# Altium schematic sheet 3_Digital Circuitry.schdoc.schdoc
size 431 x 309 mm; Symbol: Sheet-Symbol-Custom; Device: Sheet-Symbol-Custom; @Page Count: 4; @Create Date: 2024-03-28; Drawn: Thomas Crisafulli; @Page No: 2; @Page Name: Digital Circuitry; @Project Name: OhmmeterV1.1_Release; @Schematic Name: Schematic 1; Page Size: A3; @Update Date: 2024-03-27
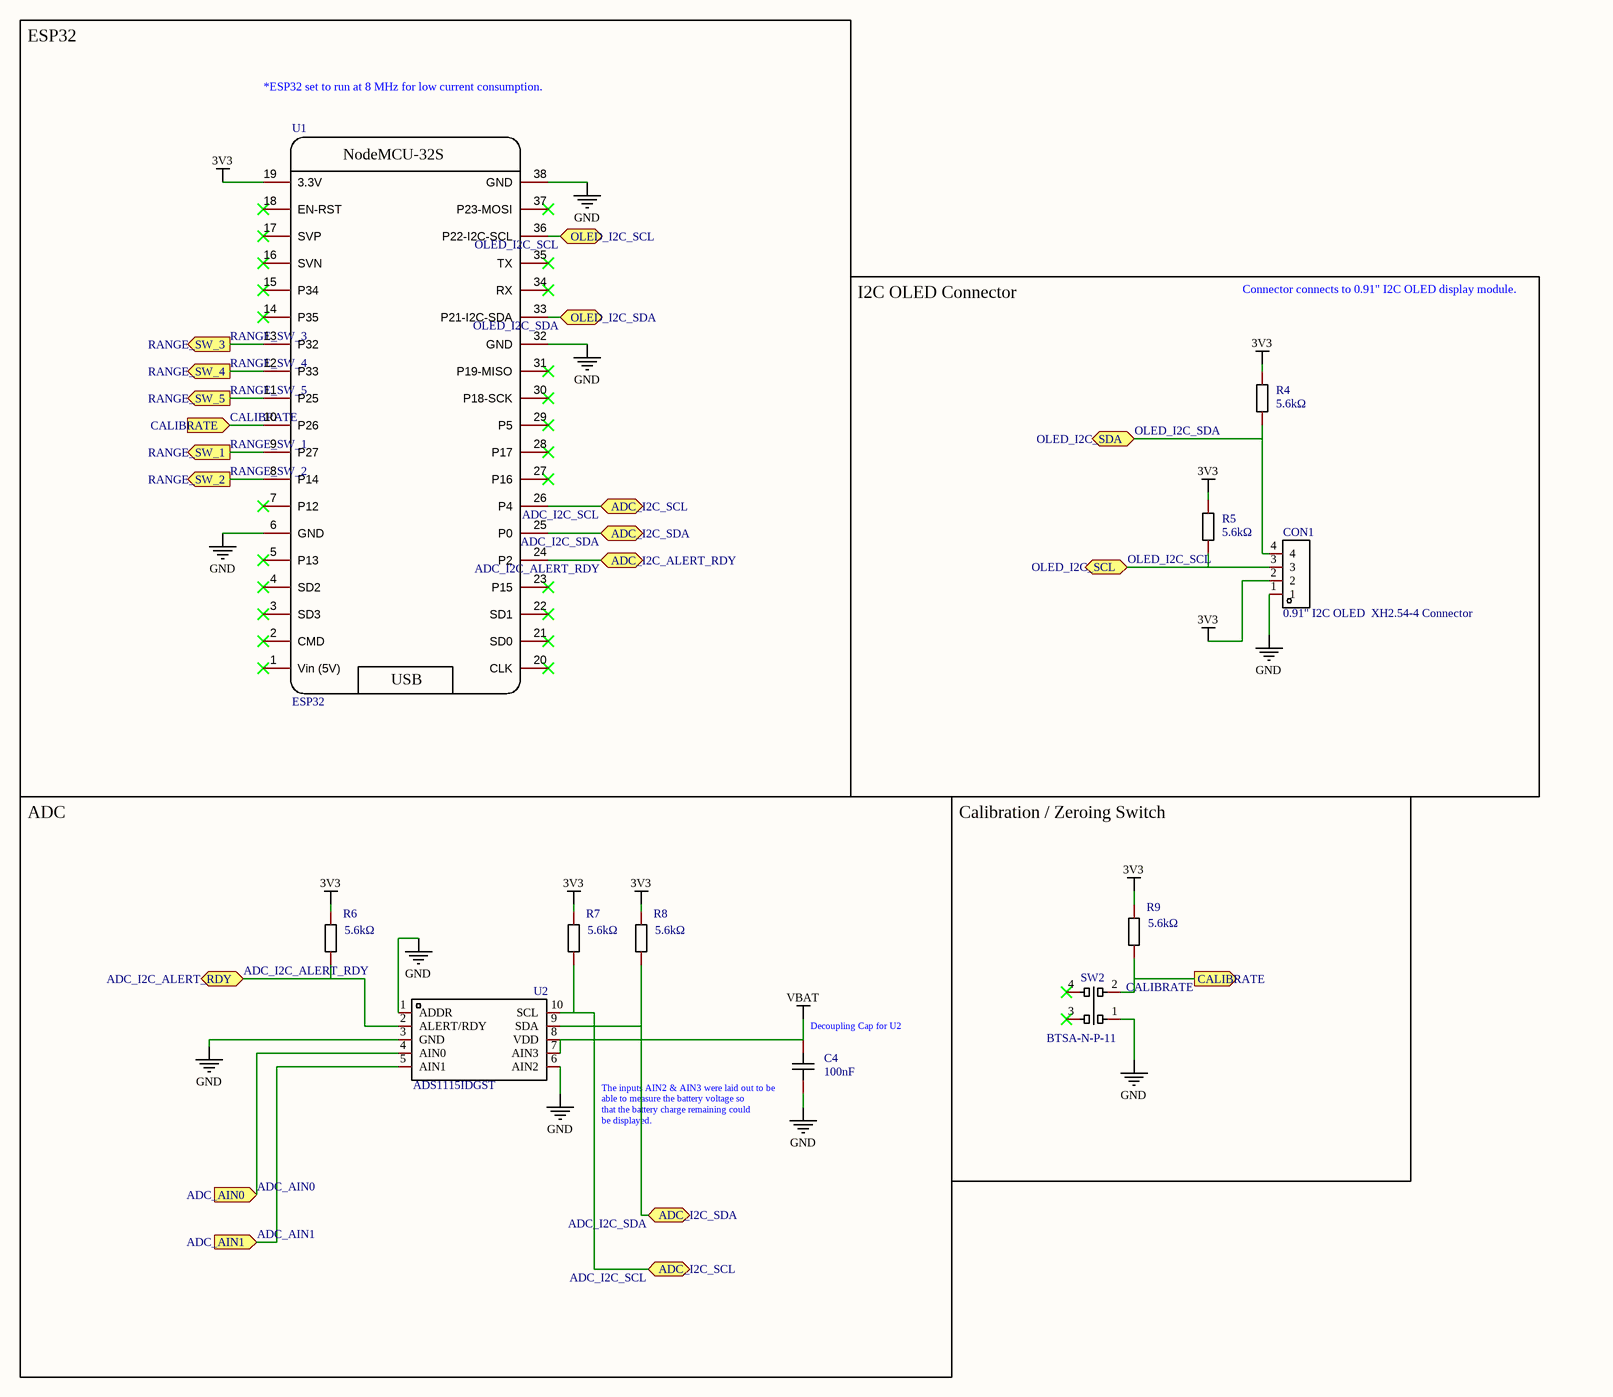
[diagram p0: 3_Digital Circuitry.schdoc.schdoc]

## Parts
C4  100nF  [C0603]
CON1  0.91" I2C OLED  XH2.54-4 Connector  [CONN-TH_XH2.54-4]
R4  5.6kΩ  [R0603]
R5  5.6kΩ  [R0603]
R6  5.6kΩ  [R0603]
R7  5.6kΩ  [R0603]
R8  5.6kΩ  [R0603]
R9  5.6kΩ  [R0603]
SW2  BTSA-N-P-11  [SW-TH_BTSA-X-P-11]
U1  ESP32  [NODEMCU-32SLUA]
U2  ADS1115IDGST  [VSSOP-10_L3.0-W3.0-P0.50-LS4.9-BL]

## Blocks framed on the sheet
ESP32: U1
I2C OLED Connector: CON1 R4 R5
ADC: C4 R6-R8 U2
Calibration / Zeroing Switch: R9 SW2

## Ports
ADC_AIN0 (in), ADC_AIN1 (in), ADC_I2C_ALERT_RDY (bidir), ADC_I2C_SCL (bidir), ADC_I2C_SDA (bidir), CALIBRATE (in), CALIBRATE (out), OLED_I2C_SCL (bidir), OLED_I2C_SDA (bidir), RANGE_SW_1 (out), RANGE_SW_2 (out), RANGE_SW_3 (out), RANGE_SW_4 (out), RANGE_SW_5 (out)

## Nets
3V3: CON1.2 R4.1 R5.2 R6.2 R7.2 R8.2 R9.2 U1.19(3.3V)
GND: C4.1 CON1.1 SW2.1 U1.6(GND) U1.32(GND) U1.38(GND) U2.1(ADDR) U2.3(GND) U2.6(AIN2)
VBAT: C4.2 U2.7(AIN3) U2.8(VDD)
ADC_AIN0: U2.4(AIN0) ; port ADC_AIN0
ADC_AIN1: U2.5(AIN1) ; port ADC_AIN1
ADC_I2C_ALERT_RDY: R6.1 U1.24(P2) U2.2(ALERT/RDY) ; port ADC_I2C_ALERT_RDY
ADC_I2C_SCL: R7.1 U1.26(P4) U2.10(SCL) ; port ADC_I2C_SCL
ADC_I2C_SDA: R8.1 U1.25(P0) U2.9(SDA) ; port ADC_I2C_SDA
CALIBRATE: R9.1 SW2.2 U1.10(P26) ; port CALIBRATE
OLED_I2C_SCL: CON1.3 R5.1 U1.36(P22-I2C-SCL) ; port OLED_I2C_SCL
OLED_I2C_SDA: CON1.4 R4.2 U1.33(P21-I2C-SDA) ; port OLED_I2C_SDA
RANGE_SW_1: U1.9(P27) ; port RANGE_SW_1
RANGE_SW_2: U1.8(P14) ; port RANGE_SW_2
RANGE_SW_3: U1.13(P32) ; port RANGE_SW_3
RANGE_SW_4: U1.12(P33) ; port RANGE_SW_4
RANGE_SW_5: U1.11(P25) ; port RANGE_SW_5

Not connected (* = marked no-connect by the designer): SW2 3* 4*; U1 1(Vin_(5V))* 2(CMD)* 3(SD3)* 4(SD2)* 5(P13)* 7(P12)* 14(P35)* 15(P34)* 16(SVN)* 17(SVP)* 18(EN-RST)* 20(CLK)* 21(SD0)* 22(SD1)* 23(P15)* 27(P16)* 28(P17)* 29(P5)* 30(P18-SCK)* 31(P19-MISO)* 34(RX)* 35(TX)* 37(P23-MOSI)*

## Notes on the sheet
- *ESP32 set to run at 8 MHz for low current consumption.
- Connector connects to 0.91" I2C OLED display module.
- (near C4) Decoupling Cap for U2
- The inputs AIN2 & AIN3 were laid out to be
  able to measure the battery voltage so
  that the battery charge remaining could
  be displayed.

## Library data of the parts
C4 = CC0603KRX7R9BB104: Manufacturer: YAGEO(国巨); Add into BOM: yes; Tolerance: ±10%; Description: Capacitance: Tolerance:±10% Tolerance:±10% Voltage Rated: Temperature Coefficient:
CON1 = XH2.54-4_C9900012082: Add into BOM: yes
R4-R9 = RMC06035.6K1%N: Manufacturer: Tyohm(幸亚电阻); Add into BOM: yes; Tolerance: ±1%; Power(Watts): 0.1W; Description: Resistance:5.6kΩ Tolerance:±1% Power(Watts):0.1W
SW2 = BTSA-N-P-11: Manufacturer: ROCPU Switches(台普); Symbol: BTSA-N-P-11_C2888323; Add into BOM: yes; Contact Current: 100mA; Insulation Resistance: 100MΩ; Self Lock / No Lock: No lock; Actuator Style: Square Plunger; Actuator/Cap Color: Blue; With Lamp: No; Pin Style: PCPin; Operating Force: 250gf@±50gf; Mechanical Life: 10000; Description: Contact Current:100mA Voltage Rating (AC):- Voltage Rating (DC):- Insulation Resistance:100MΩ Circuit:- Mounting Style:Straight Self Lock / No Lock:No lock Actuator Style:Square Plunger Actuator/Cap Color:Blue With Lamp:No Pin Style:PCPin Operating Force:
U1 = ESP32: Manufacturer: Ai-Thinker; Add into BOM: yes; Pin Type: IN
U2 = ADS1115IDGST: Manufacturer: TI(德州仪器); Add into BOM: yes; Description: Number of Bits:- Sampling Rate (Per Second): Number of Inputs: Input Type: Data Interface: Voltage - Supply: Reference Type:
